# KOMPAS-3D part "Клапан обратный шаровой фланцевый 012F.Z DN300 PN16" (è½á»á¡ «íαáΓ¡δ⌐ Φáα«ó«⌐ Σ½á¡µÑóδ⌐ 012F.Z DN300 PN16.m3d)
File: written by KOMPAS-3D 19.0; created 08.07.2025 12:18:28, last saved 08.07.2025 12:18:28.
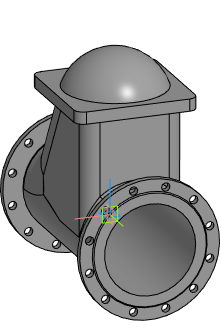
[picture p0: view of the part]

Document properties: Полное имя файла: E:\Dendor Работа Сачек\3D для проектировщиков\5.3 Тип 012F, 012F.Z Клапан обратный шаровой фланцевый\stp_Клапан обратный шаровой фланцевый 012F.Z PN10_16\Клапан обратный шаровой фланцевый 012F.Z DN300 PN16.m3d

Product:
- Part/product: Клапан обратный шаровой фланцевый 012F.Z DN300 PN16

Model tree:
1. Операция без истории:1  (labels: Клапан обратный шаровой фланцевый 012F.Z DN300 PN16)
